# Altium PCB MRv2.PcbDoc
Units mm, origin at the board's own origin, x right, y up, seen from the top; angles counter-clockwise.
Board outline 58.67 x 73.25 mm, 2 copper layers (Top Layer, Bottom Layer); 27 components, 29 nets, 132 pads, 15 vias.
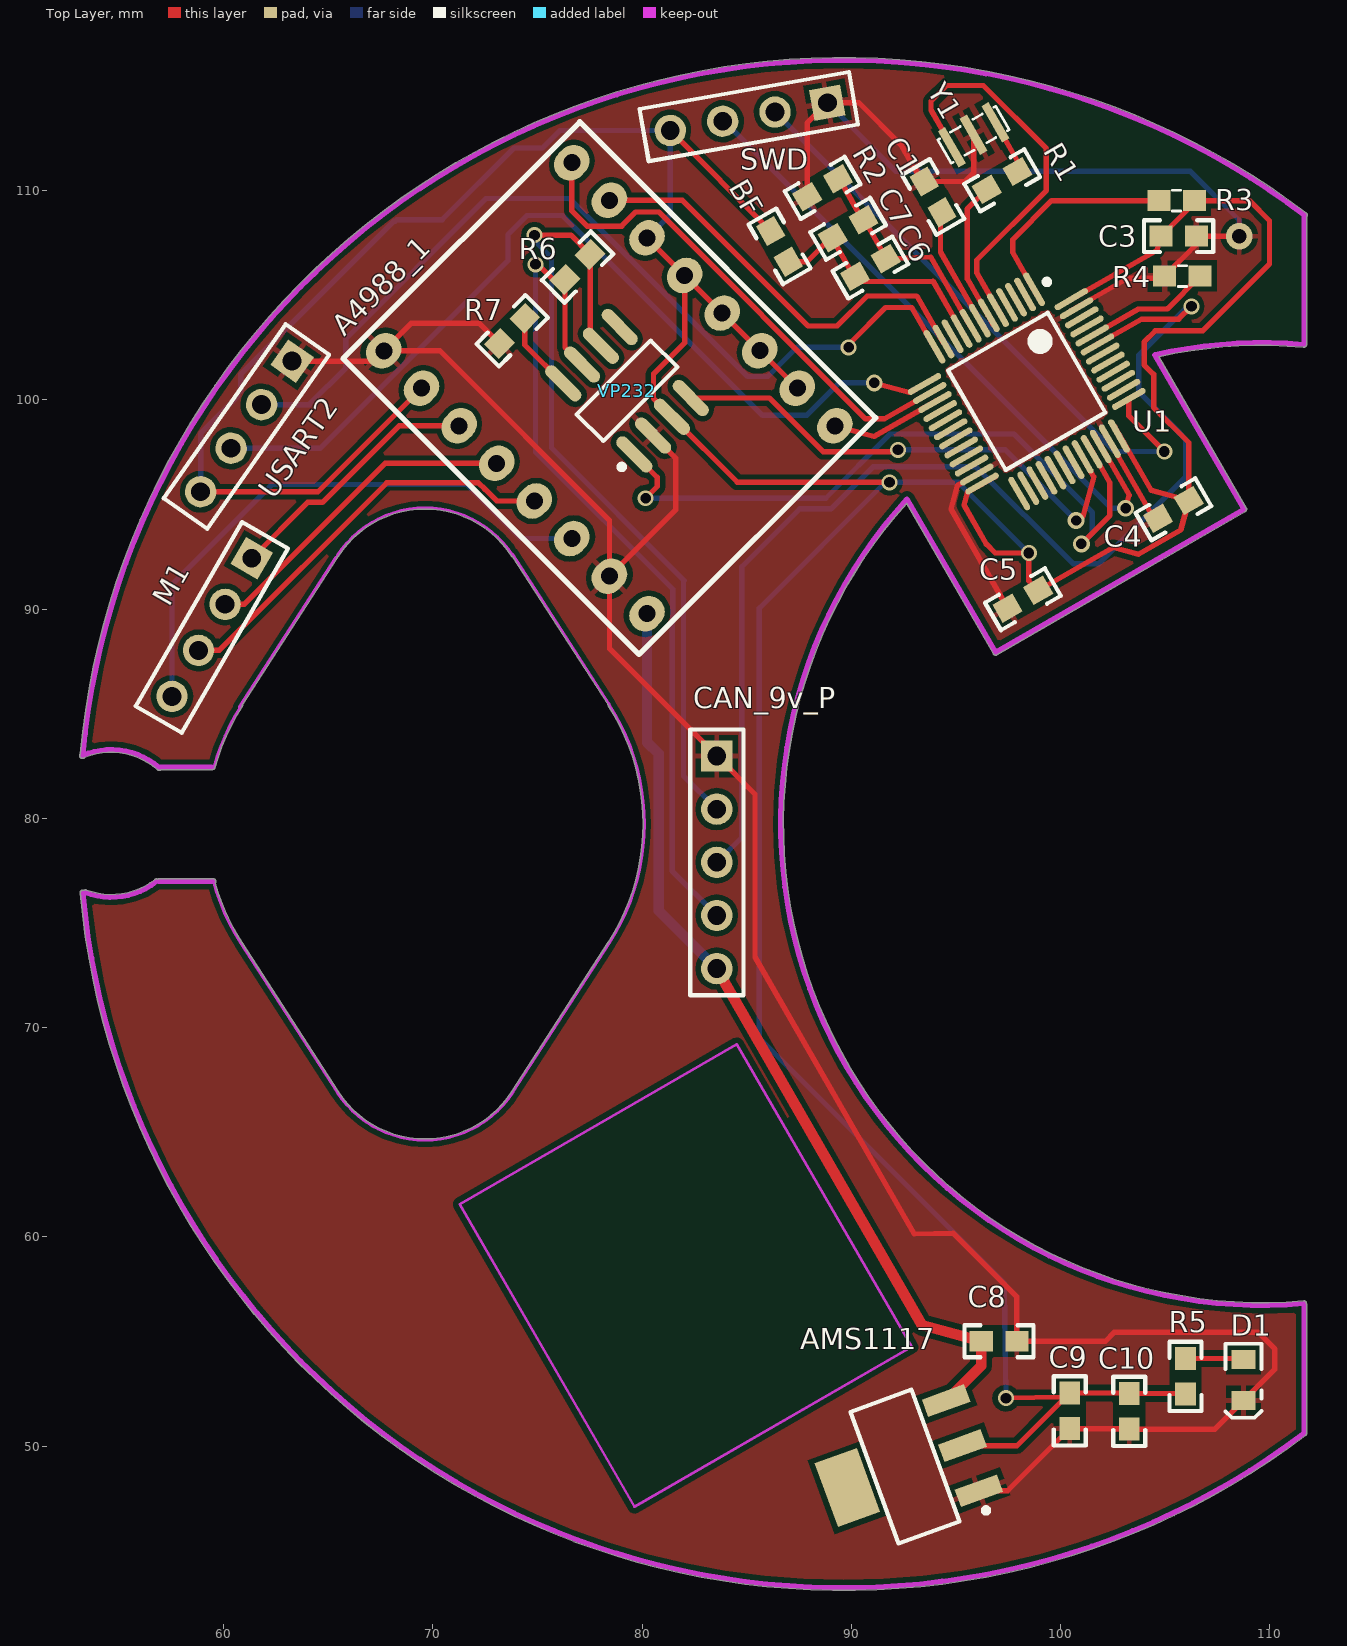
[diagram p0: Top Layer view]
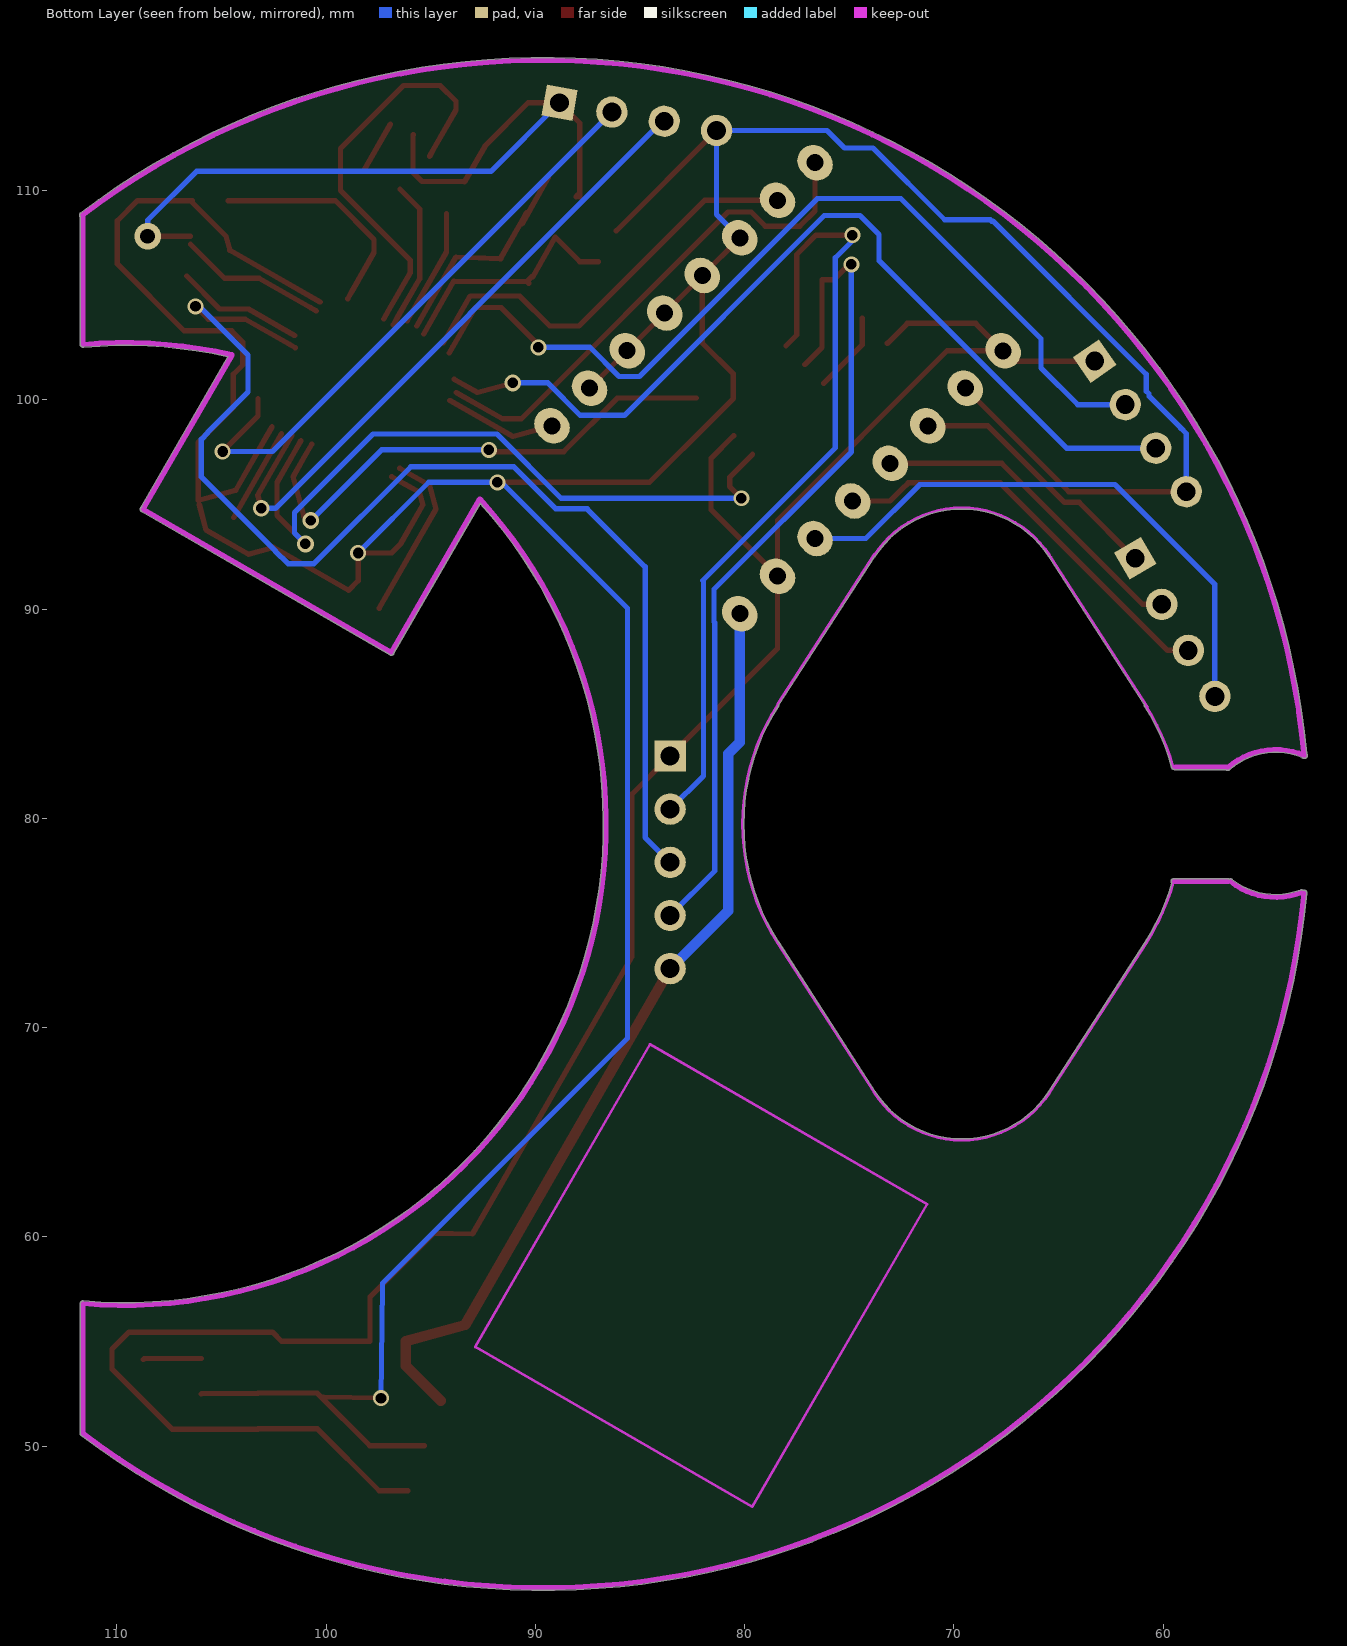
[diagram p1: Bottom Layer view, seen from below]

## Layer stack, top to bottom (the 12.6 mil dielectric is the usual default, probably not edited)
Top Layer: signal copper 0.0356
Dielectric: dielectric 0.32, FR-4, Dk 4.8
Bottom Layer: signal copper 0.0356

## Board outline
53.144,76.434 cw(c53.271,76.446) 53.322,76.563 cw(c53.392,76.457) 53.437,76.576 ccw(c54.623,79.733) 56.711,77.084 cw(c56.79,76.984) 56.853,77.095 cw(c56.921,76.987) 56.921,77.115 59.495,77.115 cw(c59.495,76.987) 59.623,76.987 cw(c59.495,76.987) 59.593,76.905 ccw(c69.623,79.733) 60.867,74.082 65.476,66.941 ccw(c65.422,66.906) 65.476,66.941 ccw(c69.623,69.618) 65.476,66.941 ccw(c69.623,69.618) 73.77,66.941 ccw(c69.623,69.618) 73.77,66.941 78.379,74.082 ccw(c69.623,79.733) 80.044,79.733 ccw(c69.623,79.733) 78.379,85.384 cw(c78.433,85.418) 78.371,85.435 cw(c78.419,85.478) 78.365,85.443 73.813,92.496 cw(c73.824,92.559) 73.77,92.525 ccw(c69.623,89.848) 65.476,92.525 cw(c65.422,92.559) 65.416,92.496 cw(c65.359,92.466) 65.423,92.466 cw(c65.359,92.466) 65.413,92.431 60.893,85.427 cw(c60.839,85.393) 60.903,85.393 cw(c60.839,85.393) 60.892,85.358 ccw(c69.648,79.707) 59.582,82.405 cw(c59.521,82.421) 59.502,82.36 cw(c59.411,82.448) 59.411,82.321 56.999,82.321 cw(c56.922,82.423) 56.839,82.327 ccw(c54.623,79.784) 53.364,82.913 cw(c53.269,82.998) 53.245,82.873 cw(c53.243,83) 53.149,83.087 cw(c89.623,79.733) 111.733,108.934 cw(c111.656,108.832) 111.784,108.832 cw(c111.656,108.832) 111.75,108.746 111.75,102.647 cw(c111.623,102.647) 111.617,102.52 cw(c111.61,102.647) 111.599,102.52 ccw(c109.623,79.733) 104.694,102.068 108.803,94.95 cw(c108.693,94.886) 108.82,94.886 cw(c108.693,94.886) 108.82,94.886 cw(c108.757,94.776) 108.884,94.776 cw(c108.757,94.776) 108.82,94.665 96.96,87.818 ccw(c96.897,87.928) 96.96,87.818 96.955,87.815 cw(c96.892,87.925) 96.768,87.896 92.638,95.051 ccw(c109.623,79.733) 111.607,56.947 cw(c111.618,56.82) 111.746,56.82 cw(c111.618,56.82) 111.745,56.806 cw(c111.623,56.769) 111.75,56.769 111.75,50.654 cw(c111.63,50.613) 111.757,50.613 cw(c111.63,50.613) 111.707,50.512 cw(c89.623,79.733)

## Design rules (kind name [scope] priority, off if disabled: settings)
Clearance [All] p1: gap=0.254
PolygonConnect [All] p1: connectstyle=Relief reliefconductorwidth=0.254 reliefentries=4 polygonreliefangle="90 Angle" airgapwidth=0.254
RoutingVias [All] p1: holewidth=0.711 width=1.27 viastyle="Through Hole" minholewidth=0.711 minwidth=1.27 maxholewidth=0.711 maxwidth=1.27
SolderMaskExpansion [All] p1: expansion=0.102
Width [All] p1: maxlimit=0.254 minlimit=0.254 preferedwidth=0.254
28 further rules are at their usual default settings.

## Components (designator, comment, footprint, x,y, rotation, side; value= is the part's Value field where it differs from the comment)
A4988_1 "stepstrick_driver" A4988 78.435,100.559 r45 top
AMS1117 "ASM1117" SOT223 92.558,49.022 r200 top
BF "BF" R1608[0603] 86.563,107.34 r120 top
C1 "cap smd" C1608[0603]N 93.904,109.703 r300 top
C3 "cap smd" C1608[0603]N 105.639,107.823 r0 top
C4 "cap smd" C1608[0603]N 105.385,94.767 r210 top
C5 "cap smd" C1608[0603]N 98.196,90.475 r210 top
C6 "cap smd" C1608[0603]N 90.907,106.324 r30 top
C7 "cap smd" C1608[0603]N 89.84,108.179 r30 top
C8 "cap smd" C1608[0603]N 97.053,55.016 r0 top
C9 "cap smd" C1608[0603]N 100.432,51.689 r270 top
C10 "cap smd" C1608[0603]N 103.276,51.664 r270 top
CAN_9v_P "H_P" HDR1X5 83.566,82.982 r270 top
D1 "LED" D1608[0603] 108.737,53.162 r270 top
M1 "Motor1" HDR1X4 61.341,92.431 r240 top
R1 "RES1" R1608[0603] 97.206,110.49 r210 top
R2 "RES1" R1608[0603] 88.621,110.134 r210 top
R3 "RES1" 1608[0603] 105.537,109.525 r180 top
R4 "RES1" 1608[0603] 105.816,105.918 r0 top
R5 "RES1" R1608[0603] 105.969,53.34 r270 top
R6 "RES1" R1608[0603] 76.911,106.35 r225 top
R7 "RES1" R1608[0603] 73.787,103.302 r225 top
SWD "Header 4" HDR1X4 88.849,114.198 r190 top
U1 "STM32F103C8T6" LQFP48_N 98.374,100.406 r300 top
USART2 "Header 4" HDR1X4 63.271,101.854 r235 top
VP232 "VP230" VP232 79.273,100.432 r135 top
Y1 "CRYSTAL_8M" Crystal_C 95.834,112.674 r30 top

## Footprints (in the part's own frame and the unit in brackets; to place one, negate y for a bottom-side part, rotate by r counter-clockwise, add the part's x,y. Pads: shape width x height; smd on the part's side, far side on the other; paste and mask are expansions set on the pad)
1608[0603] [mm] "Chip Capacitor; Body 1.6 x 0.8 mm (LxW typ)"
  rect 1.1x1 smd: 1(-0.85,0) 2(0.85,0)
  silkscreen extent -0.2,-0.5 0.2,0.5
A4988 [mil]
  oval 70x60 hole 32: 1(-250.39,350) 2(-250,250) 3(-250,150) 4(-250,50) 5(-250,-50) 6(-250,-150) 7(-250,-250) 8(-250,-350) 9(250,350) 10(250,250) 11(250,150) 12(250,50) 13(250,-50) 14(250,-150) 15(250,-250) 16(250,-350)
  silkscreen extent -315,-394 315,394
C1608[0603]N [mm] "Chip Capacitor; Body 1.6 x 0.8 mm (LxW typ)"
  rect 1.1x1 smd: 1(-0.85,0) 2(0.85,0)
  silkscreen extent -1.65,-0.76 1.65,0.76, body extent -0.8,-0.4 0.8,0.4, height 0.8
Crystal_C [mm] "含电容晶振，村田 3.2X1.3mm"
  rect 0.4x2 smd: 1(-1.2,0) 2(0,0) 3(1.2,0)
  silkscreen extent -1.6,-0.65 1.6,0.65
D1608[0603] [mm]
  rect 0.9x1.15 smd: 1(-0.98,0) 2(0.98,0)
  silkscreen extent -1.73,-0.86 1.8,0.86, body extent -0.8,-0.4 0.8,0.4, height 0.8
HDR1X4 [mm] "Connector; Header; 4 Position"
  rect 1.5x1.5 hole 0.9: 1(0,0)
  round 1.5 hole 0.9: 2(2.54,0) 3(5.08,0) 4(7.62,0)
  silkscreen extent -1.27,-1.27 8.89,1.27
HDR1X5 [mm] "Connector; Header; 5 Position"
  rect 1.5x1.5 hole 0.9: 1(0,0)
  round 1.5 hole 0.9: 2(2.54,0) 3(5.08,0) 4(7.62,0) 5(10.16,0)
  silkscreen extent -1.27,-1.27 11.43,1.27
LQFP48_N [mm] "Thin QFP, 48-Leads, Body 7x7mm, Pitch 0.5mm, IPC Medium Density"
  oval 1.8x0.3 smd: 1(-4.05,2.75) 2(-4.05,2.25) 3(-4.05,1.75) 4(-4.05,1.25) 5(-4.05,0.75) 6(-4.05,0.25) 7(-4.05,-0.25) 8(-4.05,-0.75) 9(-4.05,-1.25) 10(-4.05,-1.75) 11(-4.05,-2.25) 12(-4.05,-2.75) 25(4.05,-2.75) 26(4.05,-2.25) 27(4.05,-1.75) 28(4.05,-1.25) 29(4.05,-0.75) 30(4.05,-0.25) 31(4.05,0.25) 32(4.05,0.75) 33(4.05,1.25) 34(4.05,1.75) 35(4.05,2.25) 36(4.05,2.75)
  oval 0.3x1.8 smd: 13(-2.75,-4.05) 14(-2.25,-4.05) 15(-1.75,-4.05) 16(-1.25,-4.05) 17(-0.75,-4.05) 18(-0.25,-4.05) 19(0.25,-4.05) 20(0.75,-4.05) 21(1.25,-4.05) 22(1.75,-4.05) 23(2.25,-4.05) 24(2.75,-4.05) 37(2.75,4.05) 38(2.25,4.05) 39(1.75,4.05) 40(1.25,4.05) 41(0.75,4.05) 42(0.25,4.05) 43(-0.25,4.05) 44(-0.75,4.05) 45(-1.25,4.05) 46(-1.75,4.05) 47(-2.25,4.05) 48(-2.75,4.05)
  silkscreen extent -4.17,-2.75 2.75,3.57, body extent -3.5,-3.5 3.5,3.5, height 1.6
R1608[0603] [mm] "Chip Capacitor; Body 1.6 x 0.8 mm (LxW typ)"
  rect 1.1x1 smd: 1(-0.85,0) 2(0.85,0)
  silkscreen extent -1.65,-0.76 1.65,0.76, body extent -0.8,-0.4 0.8,0.4, height 0.5
SOT223 [mm] "SOT223, 4-Leads, Body 6.50x7.00mm (avg), Pitch 2.29mm, IPC Medium Density"
  rect 2.15x0.9 smd: 1(-2.925,2.29) 2(-2.925,0) 3(-2.925,-2.29)
  rect 2.15x3.25 smd: 4(2.925,0)
  silkscreen extent -3.05,-3.35 1.55,3.41, body extent -1.85,-3.35 1.85,3.35, height 1.8
VP232 [mm]
  oval 2.2x0.6 smd: 1(-2.394,1.898) 2(-2.394,0.628) 3(-2.394,-0.642) 4(-2.394,-1.912) 5(2.406,-1.912) 6(2.406,-0.642) 7(2.406,0.628) 8(2.406,1.898)
  silkscreen extent -2.52,-2.51 0.91,2.87, body extent -1.99,-2.51 2.01,2.49, height 1.75

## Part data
BF: "磁珠"
C1 C3 C4 C5 C6 C7 C8 C9 C10: library part CAP, "贴片无极性电容"
CAN_9v_P: library part "Header 5", "Header, 5-Pin"
D1: "蓝色 LED"
M1: library part "Header 4", "Header, 4-Pin"
SWD USART2: "Header, 4-Pin"
U1: "STM32 ARM-based 32-bit MCU Performance Line with 64 kB Flash, 20 kB Internal RAM, -40 to +85癈 Temperature, 48-Pin LQFP, Tray"
VP232: library part Component_1
Y1: library part CRYSTAL_C, "Crystal_8M"

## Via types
v1: diameter 0.762, hole 0.508, Top Layer to Bottom Layer, 10 vias
v2: diameter 0.8, hole 0.5, Top Layer to Bottom Layer, 4 vias
v3: diameter 1.27, hole 0.711, Top Layer to Bottom Layer, 1 vias

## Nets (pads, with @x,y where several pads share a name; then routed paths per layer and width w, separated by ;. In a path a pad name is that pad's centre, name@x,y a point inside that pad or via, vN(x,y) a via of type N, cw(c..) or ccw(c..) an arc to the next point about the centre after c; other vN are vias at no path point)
AGND: C6.2 C7.2 R2.1 U1.8 | length 11
  Top Layer w0.254: R2.1@89.383,110.623 C7.2@90.646,108.411 ; C7.2@90.424,108.946 90.609,108.623 91.67,106.765 C6.2@91.679,106.749 ; C6.2 C6.2@91.679,106.749 ; U1.8@95.675,103.535 93.793,106.828 C6.2@91.679,106.749
BOOT0: R4.2 U1.44 | length 6.1
  Top Layer w0.254: U1.44 103.718,104.344 105.093,104.344 ; 105.098,104.35 R4.2
CANH: CAN_9v_P.4 R6.2 VP232.7 | length 40.9
  Top Layer w0.254: v1@74.917,106.566 75.734,105.749 R6.2 76.31,102.507 VP232.7
  Bottom Layer w0.254: v1(74.905,106.477) 74.905,97.511 81.464,90.951 81.464,89.399 81.432,89.367 81.432,77.495 CAN_9v_P.4
CANL: CAN_9v_P.2 R6.1 VP232.6 | length 38.6
  Top Layer w0.254: v1(74.854,107.874) 76.589,107.874 R6.1 77.512,103.101 VP232.6
  Bottom Layer w0.254: v1(74.854,107.874) 74.854,107.605 75.667,106.792 75.667,97.714 82.007,91.373 ; 81.972,91.338 81.972,82.036 CAN_9v_P.2
CANRX: U1.32 VP232.4 | length 25
  Top Layer w0.254: VP232.4 86.087,100.091 88.648,97.53 v1@92.183,97.53 ; U1.32@100.693,97.883 101.043,97.271 101.584,96.325 101.066,94.426 v2(100.734,94.236)
  Bottom Layer w0.254: v1(92.227,97.612) 97.358,97.612 v2(100.734,94.236)
CANTX: U1.33 VP232.1 | length 34.5
  Top Layer w0.254: VP232.1 80.721,96.3 80.721,95.86 v1(80.162,95.301) v1@80.137,95.301 ; v2(100.99,93.116) 102.348,94.474 102.348,96.054 101.502,97.535 U1.33@101.201,98.061
  Bottom Layer w0.254: v1(80.162,95.301) 88.773,95.301 91.846,98.374 97.765,98.374 101.515,94.624 101.515,93.641 v2(100.99,93.116)
ER: CAN_9v_P.3 U1.43 | length 57
  Top Layer w0.254: U1.43@101.481,102.497 101.754,102.652 103.868,103.861 105.639,103.861 v1(106.248,104.47)
  Bottom Layer w0.254: CAN_9v_P.3 84.76,79.096 84.76,92.024 87.528,94.793 89.027,94.793 91.034,96.799 95.961,96.799 100.584,92.177 101.829,92.177 102.438,92.786 ; 102.475,92.823 105.969,96.317 105.969,98.117 105.673,98.412 105.673,98.441 103.734,100.381 103.734,102.142 106.061,104.47 v1(106.248,104.47)
GND: A4988_1.1 A4988_1.7 AMS1117.1 C1.1 C3.2 C4.2 C5.2 C8.2 C9.2 C10.2 CAN_9v_P.1 D1.2 R2.2 R4.1 R7.2 SWD.1 U1.23 U1.35 U1.47 USART2.1 VP232.2 Y1.2 | length 171.9
  Top Layer w0.254: USART2.1 67.158,101.854 A4988_1.1 ; R7.2 72.229,103.657 68.962,103.657 A4988_1.1 ; VP232.2 81.61,97.207 81.61,94.753 A4988_1.7 ; R2.2 87.884,113.234 SWD.1 90.358,114.198 92.39,112.166 C1.1@93.389,110.418 ; R2.2@88.012,109.782 R2.2@88.055,109.707 ; C1.1 95.42,110.439 95.849,110.868 95.849,112.659 Y1.2 ; AMS1117.1 97.463,47.871 C9.2 103.251,50.839 C10.2 107.369,50.814 D1.2 110.236,53.681 110.236,54.635 109.423,55.448 102.565,55.448 102.133,55.016 C8.2 97.903,57.138 94.869,60.173 93.009,60.14 85.395,73.381 85.395,81.153 CAN_9v_P.1 78.435,88.113 A4988_1.7 ; U1.23@96.491,96.741 95.068,95.928 94.755,94.783 C5.2 ; U1.47@100.465,104.249 100.741,104.407 103.205,105.815 104.863,105.815 R4.1 C3.2@106.489,107.44 ; U1.35@102.132,98.384 C4.2@104.422,94.377 ; C3.2 v3(108.534,107.823) ; A4988_1.1 70.333,102.348 78.435,94.245 A4988_1.7
  Bottom Layer w0.254: SWD.1 92.126,110.922 106.197,110.922 108.534,108.585 v3(108.534,107.823)
MOTOR1_1A: A4988_1.4 M1.2 | length 15.8
  Top Layer w0.254: M1.2 60.979,90.231 67.715,96.966 A4988_1.4
MOTOR1_1B: A4988_1.3 M1.1 | length 12.5
  Top Layer w0.254: M1.1 64.014,95.104 64.719,95.104 68.377,98.763 A4988_1.3
MOTOR1_2A: A4988_1.5 M1.3 | length 19.7
  Top Layer w0.254: M1.3 59.786,88.031 67.793,96.037 72.18,96.037 72.484,95.734 72.491,95.734 73.054,95.17 A4988_1.5
MOTOR1_2B: A4988_1.6 M1.4 | length 27.5
  Bottom Layer w0.254: M1.4 57.531,91.186 62.306,95.961 71.628,95.961 74.215,93.374 A4988_1.6
MOTOR1_DIR: A4988_1.9 U1.14 | length 24.5
  Top Layer w0.254: A4988_1.9 76.639,109.035 77.368,108.306 79.02,108.306 79.689,108.976 80.794,108.976 90.677,99.093 91.575,99.093 U1.14 U1.14@93.787,100.357
MOTOR1_ENB: A4988_1.16 U1.15 | length 5.4
  Top Layer w0.254: A4988_1.16 91.078,98.254 U1.15@94.091,99.976
MOTOR1_STEP: A4988_1.10 U1.11 | length 20.4
  Top Layer w0.254: A4988_1.10 81.919,109.539 87.928,103.53 89.317,103.53 90.755,104.968 93.107,104.968 93.142,104.933 94.376,102.774 U1.11@94.405,102.722
NetD1_1: D1.1 R5.1 | length 2.8
  Top Layer w0.254: R5.1 108.69,54.19 D1.1
NetR1_1: R1.1 Y1.3 | length 2.5
  Top Layer w0.254: Y1.3@96.926,113.188 R1.1@98.19,110.977
NetR3_2: R3.2 U1.1 | length 10.9
  Top Layer w0.254: U1.1@98.976,104.834 98.72,105.282 97.713,107.045 97.713,107.669 99.568,109.525 R3.2
NetR7_1: R7.1 VP232.8 | length 3.9
  Top Layer w0.254: R7.1 74.388,102.633 VP232.8
NRST: C1.2 U1.7 | length 5.6
  Top Layer w0.254: C1.2@94.254,108.892 94.254,107.076 U1.7
OSC_IN: U1.5 Y1.1 | length 19.9
  Top Layer w0.254: Y1.1@95.065,111.641 94.812,112.084 93.801,113.853 93.801,114.273 94.555,115.027 96.299,115.027 99.314,112.012 99.314,110.007 95.987,106.68 95.987,106.076 ; 95.999,106.054 97.006,104.293 U1.5@97.25,103.865
OSC_OUT: R1.2 U1.6 | length 7.2
  Top Layer w0.254: R1.2 95.529,109.125 95.529,105.797 96.542,104.025 U1.6@96.793,103.585
SWCLK: SWD.2 U1.37 | length 28.5
  Top Layer w0.254: U1.37 103.257,99.232 v1(104.953,97.536)
  Bottom Layer w0.254: SWD.2 102.569,97.536 v1(104.953,97.536)
SWDIO: SWD.3 U1.34 | length 30.9
  Top Layer w0.254: U1.34@101.633,98.315 101.936,97.786 103.271,95.449 v2(103.099,94.818)
  Bottom Layer w0.254: SWD.3@83.872,113.367 102.421,94.818 v2(103.099,94.818)
USART2_RX: U1.13 USART2.3 | length 43.7
  Top Layer w0.254: v2(91.084,100.813) 92.77,100.353 U1.13@93.888,100.992
  Bottom Layer w0.254: USART2.3 64.622,97.693 73.584,106.655 73.584,107.899 74.498,108.814 76.2,108.814 85.75,99.263 87.859,99.263 89.408,100.813 v2(91.084,100.813)
USART2_TX: U1.12 USART2.2 | length 43.2
  Top Layer w0.254: v1@89.967,102.743 91.637,104.413 92.884,104.413 93.958,102.533 U1.12@94.126,102.239
  Bottom Layer w0.254: USART2.2 64.086,99.773 65.837,101.524 65.837,102.921 72.542,109.626 76.53,109.626 85.035,101.122 86.003,101.122 87.396,102.514 v1(89.865,102.514)
V9.0: A4988_1.8 AMS1117.3 C8.1 CAN_9v_P.5 | length 44.8
  Top Layer w0.254: A4988_1.8@80.231,89.466 A4988_1.8
  Top Layer w0.5: CAN_9v_P.5 93.358,55.792 C8.1 96.203,53.855 AMS1117.3
  Bottom Layer w0.5: A4988_1.8 80.231,83.65 80.797,83.083 80.797,75.59 CAN_9v_P.5
VDD: A4988_1.2 A4988_1.11 A4988_1.12 A4988_1.13 A4988_1.14 A4988_1.15 AMS1117.2 BF.2 C3.1 C4.1 C5.1 C9.1 C10.1 R3.1 R5.2 SWD.4 U1.24 U1.36 U1.48 USART2.4 VP232.3 | length 213.3
  Top Layer w0.254: USART2.4 64.508,95.612 A4988_1.2 ; A4988_1.11 A4988_1.12 ; SWD.4 81.345,112.87 BF.2 ; A4988_1.15 A4988_1.13 A4988_1.12 ; v1(91.821,96.063) 84.55,96.063 VP232.3 80.543,100.07 80.543,101.244 82.027,102.728 A4988_1.12 ; AMS1117.2 97.915,50.022 C9.1 ; U1.24@96.867,96.335 96.251,95.983 95.548,95.581 95.382,94.974 96.448,93.108 96.872,92.685 v1(98.476,92.685) 98.476,91.357 C5.1 102.524,92.952 103.716,92.627 105.74,93.784 C4.1@106.07,94.996 ; v1(97.384,52.299) 100.14,52.349 100.191,52.299 C9.1 ; U1.48@100.287,104.681 104.604,107.148 C3.1 106.387,109.421 R3.1 109.017,109.525 109.982,108.56 109.982,106.502 106.782,103.302 104.521,103.302 103.988,102.768 103.988,101.675 104.444,101.219 104.444,99.642 106.121,97.965 C4.1 104.322,95.683 102.826,98.3 U1.36@102.589,98.714 ; R5.2 105.945,52.514 C10.1 103.251,52.539 C9.1
  Bottom Layer w0.254: USART2.4 58.901,98.394 59.156,98.649 59.156,98.653 60.684,100.181 60.684,100.292 60.812,100.421 60.812,101.223 68.133,108.544 68.205,108.544 68.272,108.61 70.442,108.61 73.871,112.039 75.235,112.039 76.071,112.875 SWD.4 81.345,108.857 A4988_1.11 ; 97.307,57.633 v1(97.384,52.299) ; 97.307,57.785 85.598,69.494 85.598,90.043 91.618,96.063 v1(91.821,96.063) 95.098,96.063 v1(98.476,92.685)
VDDA: BF.1 C6.1 C7.1 U1.9 | length 11.5
  Top Layer w0.254: BF.1 87.879,106.604 89.052,107.778 89.076,107.738 C6.1@90.137,105.88 ; C6.1 90.409,105.66 93.854,105.66 ; C6.1@90.308,105.581 C6.1@90.316,105.567 ; 93.898,105.686 U1.9@95.345,103.154
pads on no net: AMS1117.4 U1.2 U1.3 U1.4 U1.10 U1.16 U1.17 U1.18 U1.19 U1.20 U1.21 U1.22 U1.25 U1.26 U1.27 U1.28 U1.29 U1.30 U1.31 U1.38 U1.39 U1.40 U1.41 U1.42 U1.45 U1.46 VP232.5
copper on no net: | length 0.2
  Bottom Layer w0.254: 97.307,57.633 97.307,57.785

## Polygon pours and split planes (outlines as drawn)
GND on Top Layer "Top Overlay-No Net" (solid, remove dead copper, pour order 6): 49.225,120.625 49.682,120.625 124.308,120.625 124.308,34.544 124.054,34.29 48.031,34.29 48.031,119.075 49.581,120.625 50.292,120.625

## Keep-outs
Keep-Out Layer:
  lines w0.127: 59.495,77.019 ccw(c69.623,79.733) 60.813,74.047 65.422,66.906 ccw(c69.623,69.618) 73.824,66.906 78.433,74.047 ccw(c69.623,79.733) 78.433,85.418 ; 59.521,82.421 cw(c69.648,79.707) 60.839,85.393 ; 60.751,85.325 65.359,92.466 ; 65.422,92.559 cw(c69.623,89.848) 73.824,92.559 ; 73.81,92.618 78.419,85.478 ; 71.286,61.561 84.525,69.204 92.874,54.743 79.635,47.1 71.286,61.561
  lines w0.254: 53.243,83 cw(c54.623,79.784) 56.922,82.423 ; 53.269,82.998 cw(c89.623,79.733) 111.656,108.832 ; 53.271,76.446 ccw(c89.623,79.733) 111.63,50.613 ; 53.392,76.457 ccw(c54.623,79.733) 56.79,76.984 ; 56.921,76.987 59.495,76.987 ; 56.921,82.448 59.411,82.448 ; 92.655,95.26 ccw(c109.623,79.733) 111.618,56.82 ; 92.674,95.243 96.897,87.928 ; 96.892,87.925 108.757,94.776 ; 104.5,102.15 108.693,94.886 ; 104.515,102.159 cw(c109.623,79.733) 111.61,102.647 ; 111.623,50.622 111.623,56.769 ; 111.623,102.647 111.623,108.788

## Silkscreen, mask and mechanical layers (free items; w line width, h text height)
Mechanical 1:
  lines w0.127: 92.521,94.354 96.628,87.241 109.618,94.741 105.512,101.854 cw(c109.623,79.733) 112.623,102.032 ; 92.521,94.354 ccw(c109.623,79.733) 112.623,57.434 ; 112.623,57.434 112.623,50.114 cw(c89.623,79.733) 52.162,78.017 ccw(c54.623,79.733) 52.162,81.449 cw(c89.623,79.733) 112.623,109.351 112.623,102.032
